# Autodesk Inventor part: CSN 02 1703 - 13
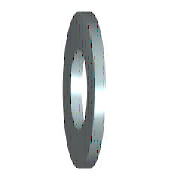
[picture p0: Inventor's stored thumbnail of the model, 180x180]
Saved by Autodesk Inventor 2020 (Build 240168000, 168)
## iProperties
Created: 2019-01
Part Number: CSN 02 1703 - 13
Material: Ocel, měkká
Description: Podložky pro šrouby s válcovou a půlkulovou hlavou
Document SubType Name: Modeling
Standard: CSN 02 1703
Designer: doma
Standards Organization: CSN
Language: cs-CZ
Size Designation: 13
Categories: <MemberInstance><Categories><Category DisplayName="Spojovací materiál" InternalName="e4da775c-781d-43d5-af7c-5136215cf5a6" Mnemonic="FSTN"><Category DisplayName
Density: 7.85 g/cm^3
Appearance: Pololeštěná
IsCustomPart: 0
Author: doma
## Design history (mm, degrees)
sketch "Náčrt"
  geometry: C1 r 10 at (0, 0); C2 r 6.5 at (0, 0); 1 further point
  constraints: 2 centre point, 2 coincident
  dimensions: "d0" = 13 diameter of C2 (= SD1); "d1" = 20 diameter of C1 (= SD2)
extrude "Těleso" new body sketch "Náčrt" distance "d2" = 2.5 (= SD); taper "d3" = 0 deg
workaxis "Work Axis1"
workplane "Work Plane1"
body "Solid1"
other parameters: "SD1" = 13 [user parameter; used in 1 equation term], "SD2" = 20 [user parameter; used in 1 equation term], "SD" = 2.5 [user parameter; used in 1 equation term], "d4" = 0, "d5" = 0, "d6" = 0, "d7" = 0, "NND" = 12 [user parameter]
